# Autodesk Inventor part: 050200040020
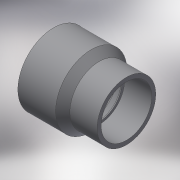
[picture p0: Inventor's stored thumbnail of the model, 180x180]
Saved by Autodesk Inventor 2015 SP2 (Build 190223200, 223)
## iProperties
Created: 2017-10
Part Number: 050200040020
Material: Generic
Description: PLASSON REDUCING SOCKET M.F.40(32)20 CEMENTED
Document SubType Name: Modeling
Designer: KIM
Density: 1 g/cm^3
Appearance: Default
Author: KIM
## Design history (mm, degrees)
derived "050200.ipt"
feature "Solid1::050200.ipt"
tag "TaggingFeature1"
body "Solid1"
other parameters: "d0" = 52, "d1" = 26, "d2" = 16, "d3" = 22, "d5" = 26, "d6" = 32, "d8" = 18, "d9" = 45 deg, "d12" = 0.32, "d_" = 32, "L_" = 26, "l_" = 22, "l_1" = 16, "E_" = 26, "H_" = 52, "d11" = 6.10726
